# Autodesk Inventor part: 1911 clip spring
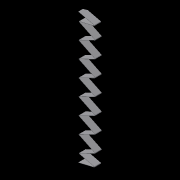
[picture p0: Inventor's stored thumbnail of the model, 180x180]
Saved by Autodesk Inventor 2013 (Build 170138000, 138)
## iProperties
Created: 2013-03
Part Number: 1911 clip spring
Material: Generic
Document SubType Name: Modeling
Designer: John
Density: 1 g/cm^3
Author: John
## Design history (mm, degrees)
sketch "Sketch1"
  geometry: L1 (0.06, 101.847)-(24.339, 95.991); L2 (24.339, 94.509)-(2.133, 89.153); L3 (2.032, 88.202)-(25.489, 76.886); L4 (25.489, 75.514)-(1.533, 63.958); L5 (1.533, 63.042)-(25.489, 51.486); L6 (25.489, 50.114)-(1.533, 38.558); L7 (1.533, 37.642)-(25.489, 26.086); L8 (25.489, 24.714)-(1.533, 13.158); L9 (1.533, 12.242)-(25.489, 0.686); L10 (-0.06, 101.353)-(23.196, 95.744); L11 (23.196, 94.756)-(1.323, 89.48); L12 (1.171, 88.053)-(24.794, 76.658); L13 (24.794, 75.742)-(0.838, 64.186); L14 (0.838, 62.814)-(24.794, 51.258); L15 (24.794, 50.342)-(0.838, 38.786); L16 (0.838, 37.414)-(24.794, 25.858); L17 (24.794, 24.942)-(0.838, 13.386); L18 (0.838, 12.014)-(24.794, 0.458); L19 (1.171, -88.053)-(24.794, -76.658); L20 (2.032, -88.202)-(25.489, -76.886); L21 (24.794, -75.742)-(0.838, -64.186); L22 (25.489, -75.514)-(1.533, -63.958); L23 (25.489, -24.714)-(1.533, -13.158); L24 (1.533, -12.242)-(25.489, -0.686); L25 (24.794, -24.942)-(0.838, -13.386); L26 (0.838, -12.014)-(24.794, -0.458); L27 (0.06, -101.847)-(24.339, -95.991); L28 (24.339, -94.509)-(2.133, -89.153); L29 (23.196, -94.756)-(1.323, -89.48); L30 (-0.06, -101.353)-(23.196, -95.744); L31 (1.533, -63.042)-(25.489, -51.486); L32 (25.489, -50.114)-(1.533, -38.558); L33 (1.533, -37.642)-(25.489, -26.086); L34 (0.838, -62.814)-(24.794, -51.258); L35 (24.794, -50.342)-(0.838, -38.786); L36 (0.838, -37.414)-(24.794, -25.858); A1 r 0.762 centre (1.169, 12.7) between (0.838, 13.386) and (0.838, 12.014); A2 r 0.762 centre (25.158, 25.4) between (25.489, 24.714) and (25.489, 26.086); A3 r 0.762 centre (1.169, 38.1) between (0.838, 38.786) and (0.838, 37.414); A4 r 0.762 centre (25.158, 50.8) between (25.489, 50.114) and (25.489, 51.486); A5 r 0.762 centre (1.169, 63.5) between (0.838, 64.186) and (0.838, 62.814); A6 r 0.762 centre (25.158, 76.2) between (25.489, 75.514) and (25.489, 76.886); A7 r 0.762 centre (1.502, 88.74) between (1.323, 89.48) and (1.171, 88.053); A8 r 0.762 centre (24.161, 95.25) between (24.339, 94.509) and (24.339, 95.991); A9 r 0.254 centre (0, 101.6) between (0.06, 101.847) and (-0.06, 101.353); A10 r 0.508 centre (1.754, 12.7) between (1.533, 13.158) and (1.533, 12.242); A11 r 0.508 centre (24.573, 25.4) between (24.794, 24.942) and (24.794, 25.858); A12 r 0.508 centre (1.754, 38.1) between (1.533, 38.558) and (1.533, 37.642); A13 r 0.508 centre (24.573, 50.8) between (24.794, 50.342) and (24.794, 51.258); A14 r 0.508 centre (1.754, 63.5) between (1.533, 63.958) and (1.533, 63.042); A15 r 0.508 centre (24.573, 76.2) between (24.794, 75.742) and (24.794, 76.658); A16 r 0.508 centre (2.252, 88.659) between (2.133, 89.153) and (2.032, 88.202); A17 r 0.508 centre (23.077, 95.25) between (23.196, 94.756) and (23.196, 95.744); A18 r 0.508 centre (24.573, -76.2) between (24.794, -76.658) and (24.794, -75.742); A19 r 0.762 centre (25.158, -76.2) between (25.489, -76.886) and (25.489, -75.514); A20 r 0.508 centre (24.573, -25.4) between (24.794, -25.858) and (24.794, -24.942); A21 r 0.762 centre (25.158, -25.4) between (25.489, -26.086) and (25.489, -24.714); A22 r 0.508 centre (1.754, -12.7) between (1.533, -12.242) and (1.533, -13.158); A23 r 0.762 centre (1.169, -12.7) between (0.838, -12.014) and (0.838, -13.386); A24 r 0.508 centre (1.754, -63.5) between (1.533, -63.042) and (1.533, -63.958); A25 r 0.762 centre (1.169, -63.5) between (0.838, -62.814) and (0.838, -64.186); A26 r 0.508 centre (2.252, -88.659) between (2.032, -88.202) and (2.133, -89.153); A27 r 0.762 centre (1.502, -88.74) between (1.171, -88.053) and (1.323, -89.48); A28 r 0.762 centre (24.161, -95.25) between (24.339, -95.991) and (24.339, -94.509); A29 r 0.508 centre (23.077, -95.25) between (23.196, -95.744) and (23.196, -94.756); A30 r 0.254 centre (0, -101.6) between (-0.06, -101.353) and (0.06, -101.847); A31 r 0.762 centre (1.169, -38.1) between (0.838, -37.414) and (0.838, -38.786); A32 r 0.508 centre (1.754, -38.1) between (1.533, -37.642) and (1.533, -38.558); A33 r 0.762 centre (25.158, -50.8) between (25.489, -51.486) and (25.489, -50.114); A34 r 0.508 centre (24.573, -50.8) between (24.794, -51.258) and (24.794, -50.342); A35 r 0.508 centre (24.573, 0) between (24.794, -0.458) and (24.794, 0.458); A36 r 0.762 centre (25.158, 0) between (25.489, -0.686) and (25.489, 0.686); 1 further point
  constraints: 72 end point, 72 point on circle, 36 centre point, 36 tangent, 12 equal radius, 10 parallel
  dimensions: "d11" = 0.762 radius of A1; "d12" = 0.762 radius of A2; "d13" = 0.762 radius of A4; "d14" = 0.508 radius of A10; "d17" = 0.508 radius of A35; "d18" = 0.762 radius of A36
extrude "Extrusion2" new body sketch "Sketch1" distance "d19" = 10.16; taper "d20" = 0 deg
sketch "Sketch2"
  geometry: L1 (24.976, 10.16)-(24.976, 0) reference; L2 (-1.256, 6.032)-(6.104, 11.324); L3 (-1.256, 6.032)-(-1.256, 11.696); L4 (-1.256, 11.696)-(6.104, 11.324); 1 further point
  constraints: 6 end point, 1 parallel
extrude "Extrusion3" cut sketch "Sketch2" distance "d21" = 25.4; taper "d22" = 0 deg
body "Solid2"
